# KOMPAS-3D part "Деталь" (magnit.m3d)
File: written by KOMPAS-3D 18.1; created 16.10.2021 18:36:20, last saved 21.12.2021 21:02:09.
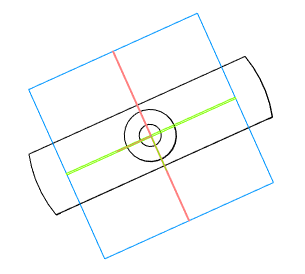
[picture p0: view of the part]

Document properties: Автор: 111; Полное имя файла: C:\Users\admin\Desktop\ffb\magnit.m3d

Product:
- Part/product: Деталь
    Масса: 0.0584065

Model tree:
1. Эскиз:1
2. Элемент выдавливания:1
     Расстояние 1 = 15
3. Эскиз:2  (with: Элемент выдавливания:1)
4. Элемент выдавливания:2
     Расстояние 2 = 10
5. Эскиз:3  (with: Элемент выдавливания:2)
6. Элемент выдавливания:4
     Расстояние 2 = 2
7. Эскиз:4  (with: Элемент выдавливания:1)
8. Элемент выдавливания:5
     Расстояние 1 = 14
9. Эскиз:6  (with: Элемент выдавливания:2)
10. Элемент выдавливания:6
     Расстояние 1 = 10
11. Эскиз:8  (with: Элемент выдавливания:1)
12. Элемент выдавливания:7
     Расстояние 2 = 20
13. Эскиз:9  (with: Элемент выдавливания:6)
14. Элемент выдавливания:8
     Расстояние 1 = 64.5
15. Эскиз:12  (with: Элемент выдавливания:8)
16. Элемент выдавливания:10
     Расстояние 2 = 10
17. Эскиз:14  (with: Элемент выдавливания:1, Элемент выдавливания:5)
18. Элемент выдавливания:12
     Расстояние 2 = 20
19. Эскиз:15  (with: Элемент выдавливания:5)
20. Элемент выдавливания:13
     Расстояние 2 = 2.5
